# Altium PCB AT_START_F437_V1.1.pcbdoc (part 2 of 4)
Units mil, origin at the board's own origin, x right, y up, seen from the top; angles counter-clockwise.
Board outline 10746.75 x 3533.35 mil, 2 copper layers (Top Layer, Bottom Layer); 198 components, 235 nets, 885 pads, 1100 vias.
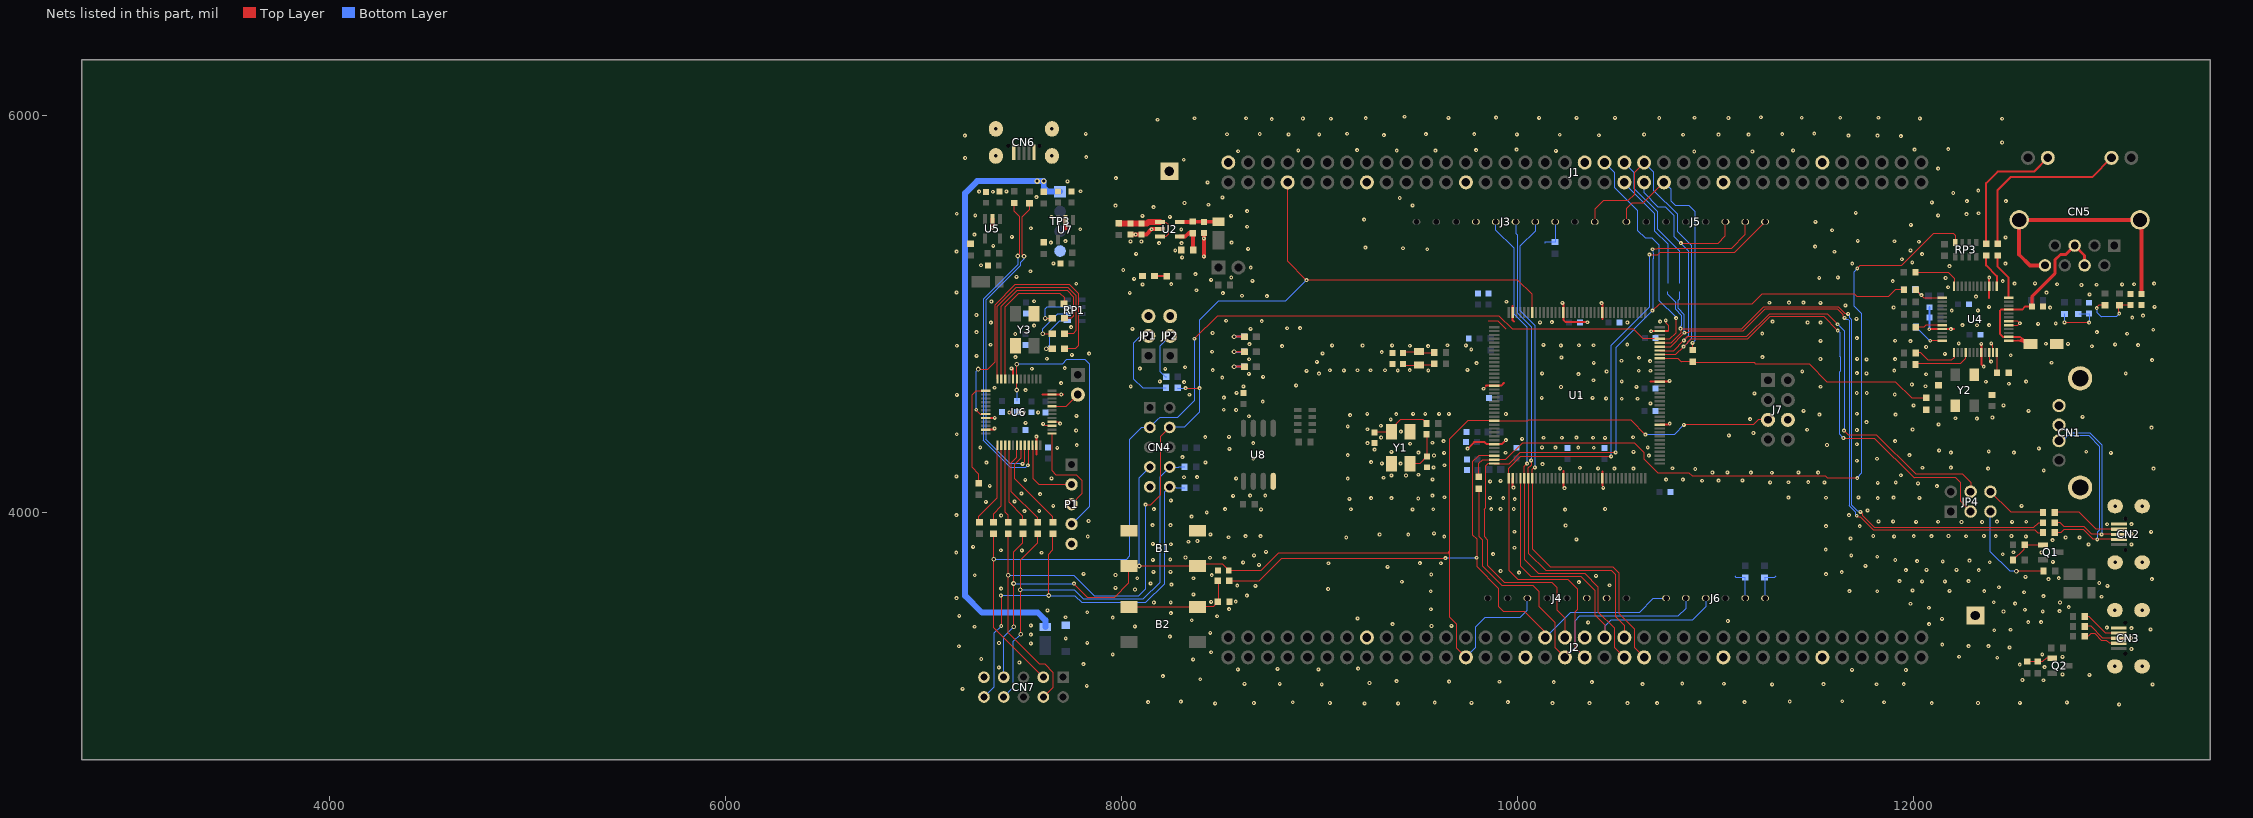
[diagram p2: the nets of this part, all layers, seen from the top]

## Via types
v1: diameter 19.69, hole 7.87, Top Layer to Bottom Layer, 1002 vias
v2: diameter 23.62, hole 11.81, Top Layer to Bottom Layer, 48 vias
v3: diameter 24, hole 12, Top Layer to Bottom Layer, 18 vias
v4: diameter 19.68, hole 7.87, Top Layer to Bottom Layer, 16 vias
v5: diameter 35.43, hole 19.69, Top Layer to Bottom Layer, 12 vias
v6: diameter 27.56, hole 15.75, Top Layer to Bottom Layer, 2 vias
v7: diameter 35.43, hole 19.68, Top Layer to Bottom Layer, 2 vias

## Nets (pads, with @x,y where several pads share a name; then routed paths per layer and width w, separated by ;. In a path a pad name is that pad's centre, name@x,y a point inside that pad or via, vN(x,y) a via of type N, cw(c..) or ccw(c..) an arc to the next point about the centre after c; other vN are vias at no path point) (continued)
$1N457: LD2.1 RP1.7 | length 200.3
  Top Layer w6: v2(7615.11,4977.88) 7649.1,4977.86 LD2.1@7649.5,4977.47
  Bottom Layer w6: v2(7615.11,4977.88) 7615.1,5027.16 7624.4,5036.47 RP1.7@7727.7,5036.47
$1N458: LD3.1 RP1.6 | length 229
  Top Layer w6: v2(7602.55,4901.02) LD3.1@7649.97,4901.01
  Bottom Layer w6: v2(7602.55,4901.02) 7602.6,4926.77 7676.8,5000.97 RP1.6@7727.7,5000.97
$1N459: LD4.1 RP1.5 | length 239.4
  Top Layer w6: v2(7619.44,4825.4) 7619.8,4825.06 LD4.1@7649.9,4825.06
  Bottom Layer w6: v2(7619.44,4825.4) 7636.6,4842.56 7636.6,4915.06 7687.1,4965.56 RP1.5@7727.7,4965.56
$1N484: J9.2 U6.44 | length 154.6
  Top Layer w6: U6.44@7648.8,4534.27 7720.2,4534.27 J9.2@7779,4593.06
$2N452: C1.2 R1.1 Y1.1 | length 309.1
  Top Layer w6: C1.2@9277.76,4402.85 9281,4406.06 Y1.1@9362.56,4406.07 9362.6,4420.4 9410.96,4468.86 9520.8,4468.86 R1.1@9542.2,4447.36
$2N453: C2.2 R3.1 Y1.3 | length 211.7
  Top Layer w6: Y1.3@9457.04,4244.65 9504.8,4244.66 C2.2@9541.38,4281.21 R3.1@9542.2,4393.36
$2N511: C3.2 R5.1 X1.2 | length 164.3
  Top Layer w6: C3.2@9421.9,4802.56 9429.9,4810.47 X1.2@9501.97,4810.51 9507.2,4805.27 R5.1@9580.8,4805.27
$2N512: C4.2 R6.1 X1.1 | length 163.6
  Top Layer w6: C4.2@9422.3,4746.97 9426.7,4742.56 X1.1@9501.97,4742.59 9575.7,4742.56 R6.1@9581.6,4748.56
$2N701: JP1.2 R13.1 | length 455.4
  Bottom Layer w6: JP1.2@8135.8,4889.36 8096.7,4889.36 8059.8,4852.36 8059.8,4674.36 8106.7,4627.36 R13.1@8226.3,4627.36
$2N702: JP2.2 R14.1 | length 244.9
  Bottom Layer w6: R14.1@8227.3,4683.36 8221.3,4683.36 8193.8,4710.86 8193.8,4837.36 JP2.2@8245.8,4889.36
$3N58: C5.1 C6.1 F1.2 U2.1 U2.3 | length 369.5
  Top Layer w6: U2.1@8180.7,5465.36 8224.1,5463.97 8235.8,5452.36 8235.8,5402.36 8223.7,5390.36 U2.3@8193.75,5390.35
  Top Layer w30: F1.2@7985.8,5458.66 7987.9,5456.47 C5.1@8045.75,5456.5 C6.1@8100.75,5456.5 8127.4,5456.47 8136.2,5465.36 8180.7,5465.36 U2.1@8193.75,5465.35
$3N81: R15.1 R16.1 U2.4 | length 160.8
  Top Layer w20: U2.4@8293.75,5390.35 8320.7,5390.36 8340.3,5409.86 8359.8,5409.86 8359.8,5323.86 R15.1@8359.2,5323.36
$3N82: C7.1 D1.2 R16.2 U2.5 | length 196.6
  Top Layer w20: U2.5@8293.75,5465.35 8324.3,5465.36 8324.7,5464.86 8359.7,5464.86 8361,5466.06 D1.2@8489.7,5466.06
$3N119: LED1.1 R10.2 | length 64.5
  Top Layer w10: LED1.1@8165.8,5192.16 R10.2@8230.3,5191.36
$3N184: B2.2 B2.4 R18.2 R19.1 | length 568
  Top Layer w6: B2.4@8037.5,3520.97 8384,3520.97 8461.8,3520.97 8488.2,3547.36 8487.2,3548.36 R19.1@8487.2,3653.36
$3N504: LED2.1 R26.2 | length 104.4
  Top Layer w10: v3(8568.19,4733.99) 8568.8,4734.56 LED2.1@8620.5,4734.56
  Bottom Layer w10: v3(8568.19,4733.99) 8568.6,4734.36 R26.2@8619.9,4734.36
$3N505: LED3.1 R27.2 | length 104.1
  Top Layer w10: v3(8568.19,4809.39) LED3.1@8620.56,4809.56
  Bottom Layer w10: v3(8568.19,4809.39) R27.2@8619.9,4809.36
$3N506: LED4.1 R28.2 | length 104.1
  Top Layer w10: v3(8568.19,4885.69) LED4.1@8620.56,4885.86
  Bottom Layer w10: v3(8568.19,4885.69) R28.2@8619.9,4885.66
$3N630: CN2.4 R29.2 | length 361.6
  Top Layer w6: R29.2@12710.1,3998.36 12836,3998.36 12921.1,3913.26 CN2.4@13036.5,3913.26
$3N657: Q1.1 R32.2 R33.1 | length 193.9
  Top Layer w6: R33.1@12503.1,3758.36 12558.1,3813.36 12558.1,3834.36 Q1.1@12653.23,3833.76
$3N714: Q2.1 R36.1 R37.2 | length 134.1
  Top Layer w6: R37.2@12572.7,3243.07 12650.3,3243.07 12668.2,3260.97 Q2.1@12699.4,3260.97
$3N779: CN3.4 R38.2 | length 208.5
  Top Layer w6: R38.2@12862,3472.36 12885.3,3472.36 12969.2,3388.47 CN3.4@13035.7,3388.47
$3N780: CN3.3 R39.2 | length 198.4
  Top Layer w6: R39.2@12862,3422.36 12895.58,3422.36 12954.98,3362.86 CN3.3@13035.7,3362.86
$3N781: CN3.2 R40.2 | length 198.7
  Top Layer w6: R40.2@12862,3372.36 12882.13,3372.36 12894.71,3384.94 12915.93,3384.94 12950,3350.86 12975.53,3350.86 12989.13,3337.26 CN3.2@13035.7,3337.26
$4N269: J6.5 R57.2 | length 163
  Bottom Layer w6: 11095.8,3678.07 11102,3671.86 11149.7,3671.86 J6.5@11149.36,3565.36
$4N270: J6.6 R59.2 | length 168.5
  Bottom Layer w6: J6.6@11249.36,3565.36 11249.35,3666.94 R59.2@11246.6,3669.69 11298.91,3669.69 11306.5,3677.28
$4N339: J3.3 R61.2 | length 161.8
  Bottom Layer w6: 10135.7,5356.66 10135.7,5361.86 10188.8,5361.86 J3.3@10189.36,5465.36
$5N126: R62.2 U4.24 | length 249.5
  Top Layer w6: R62.2@12007.3,5211.36 12173.8,5211.36 12203.5,5181.66 U4.24@12203.48,5140.68
$5N184: R69.2 U4.36 | length 162.1
  Top Layer w6: v4(12083.46,4865.2) 12083.59,4865.06 U4.36@12144.43,4865.09
  Bottom Layer w6: R69.2@12011.07,4934.54 12080.42,4865.2 v4(12083.46,4865.2)
$5N285: C46.1 R76.1 R77.1 | length 266.4
  Top Layer w6: v1(12761.53,4957.78) 12762.32,4956.99 v1(12886.04,4956.99)
  Bottom Layer w6: v1(12761.53,4957.78) 12761.5,5001.66 R76.1@12761.7,5001.86 ; R77.1@12833.6,5001.97 C46.1@12886.03,5002 v1(12886.04,4956.99)
$5N306: C47.1 R78.1 R79.1 | length 299
  Top Layer w6: v1(12924.26,5030.28) 12924.27,5033.44 12934.11,5043.28 R78.1@12964.32,5043.28 ; v1@13038.11,5001.95 13036.55,5003.52 13036.55,5042.56 13039.75,5045.77 C47.1@13094.09,5045.77
  Bottom Layer w6: v1(12924.26,5030.28) 12924.26,5008.22 12946.32,4986.15 13022.36,4986.15 v1(13038.12,5001.91)
$5N309: CN5.10 R80.1 | length 915.5
  Top Layer w10: R80.1@12423.8,5352.86 12423.8,5626.36 12488.8,5691.36 12901.1,5691.36 CN5.10@12998.63,5788.77
$5N310: CN5.11 R81.1 | length 672.4
  Top Layer w10: R81.1@12365.8,5352.86 12365.8,5661.36 12423.8,5719.36 12607.5,5719.36 CN5.11@12676.9,5788.77
$5N573: R74.2 U4.48 | length 103.7
  Top Layer w6: U4.48@12420,4806.06 12420,4705.56 R74.2@12422.3,4703.36
ATLINK_5V: CN6.1 D3.2 F2.1 TP3.1 | length 3070.1
  Bottom Layer w30: D3.2@7615.2,3419.26 7615.2,3454.57 7576.9,3492.86 7294.4,3492.86 7210.5,3576.76 7210.5,5610.56 7271,5670.97 v6(7607.18,5671.02) 7607.2,5637.36 7626.6,5618.06 TP3.1@7689.6,5618.06
  other v6: 7573.2,5671.56
ATLK_RX: CN4.10 CN7.10 R25.1 R48.1 | length 2306.3
  Top Layer w6: v1(7390.2,3578.57) 7392.2,3576.57 v1(7392.2,3424.57) ; v2@7634.7,3576.07 v2(7632.2,3578.57) 7632.2,3787.47 7653.2,3808.47 R48.1@7653.2,3892.07
  Bottom Layer w6: CN7.10@7305,3065.97 7355.5,3116.57 7355.5,3387.97 v1(7392.2,3424.57) ; v1(7390.2,3578.57) v2(7632.2,3578.57) 7763.47,3578.57 7797.92,3544.11 8122.97,3544.11 8217.14,3638.28 8217.14,4101.72 CN4.10@8242.77,4127.36 ; CN4.10@8270.7,4127.56 8275.7,4122.47 R25.1@8319.7,4122.47
ATLK_TX: CN4.8 CN7.8 R24.1 R47.1 | length 2336.5
  Top Layer w6: v2(7490.2,3383.57) 7490.2,3759.16 7577.2,3846.16 R47.1@7577.2,3892.07
  Bottom Layer w6: CN7.8@7405,3065.97 7453.54,3114.58 7453.54,3346.91 v2(7490.2,3383.57) ; v2(7488.97,3607.01) 7760.63,3607.01 7806.2,3561.45 8109.97,3561.45 8194.68,3646.16 8194.68,4179.26 CN4.8@8242.77,4227.36 8288.4,4227.36 8290.5,4229.36 R24.1@8320.3,4229.36
AVDD18: C45.1 C48.2 CN5.4 CN5.5 U4.1 U4.2 U4.9 | length 1164
  Top Layer w10: U4.1@12479.07,4865.09 12531.8,4865.06 ; 12527.8,4865.36 C45.1@12589.37,4849.35 12536.6,4884.77 U4.2@12479.07,4884.77 12450,4884.77 12434.9,4899.86 12434.9,5015.66 12441.8,5022.56 U4.9@12479.07,5022.56 12547,5022.56 12561.8,5037.36 C48.2@12598.2,5037.36
  Top Layer w15: 12542.1,4869.97 12570.1,4849.36 C45.1@12589.37,4849.35 ; C48.2@12598.2,5037.36 12598.2,5089.86 12712.3,5203.97 12712.3,5272.56 12740.7,5300.97 12767.8,5300.97 12812.8,5345.86 12862.8,5295.86 CN5.4@12862.8,5245.86
BOOT0: CN4.4 CN7.4 J1.66 R13.2 R45.1 U1.138 | length 5766.1
  Top Layer w6: R45.1@7428.2,3892.07 7428.2,3390.57 7587.8,3230.97 7613.5,3230.97 7655.6,3188.97 7655.6,3116.57 CN7.4@7605,3065.97 ; v1(8121.75,4037.36) 8147.35,4037.36 8197.04,4087.05 8197.04,4381.63 CN4.4@8242.77,4427.36 ; v1(8323.2,4625.98) v1(8394.07,4625.98) ; J1.66@8838.7,5664.56 8838.7,5266.36 v1(8933.8,5171.36) 10000.7,5171.36 10073.4,5098.66 U1.138@10073.36,5007.69
  Bottom Layer w6: v2(7427.75,3681.36) 7757.75,3681.36 7862.76,3576.35 8085.76,3576.35 8121.75,3612.35 v1(8121.75,4037.36) ; CN4.4@8242.77,4427.36 8315.3,4427.56 8392.8,4505.06 8392.8,4968.36 8489.4,5064.97 8827.4,5064.97 v1(8933.8,5171.36) ; R13.2@8281.3,4627.36 8282.6,4625.97 v1(8323.2,4625.98)
CRS_DV: R70.2 U4.37 | length 244.4
  Top Layer w6: R70.2@12007.9,4803.66 12035.8,4803.66 12074.04,4765.51 12190.63,4765.51 12203.5,4778.39 U4.37@12203.5,4806.06
EMAC_GND: C49.2 CN5.8 CN5.SH1 CN5.SH2 | length 1317
  Top Layer w20: CN5.8@12662.75,5245.9 12586.21,5245.9 12532.83,5299.27 12532.83,5475.82 CN5.SH1@13142.72,5475.79 ; CN5.SH1@13142.7,5475.86 13151.2,5467.36 C49.2@13151.2,5100.77
EMAC_NRST: R71.2 U4.40 | length 287.7
  Top Layer w6: R71.2@12014.45,4752.51 12238.7,4752.51 12262.5,4776.32 U4.40@12262.5,4806.06
GND: B1.2 B1.4 C1.1 C2.1 C3.1 C4.1 C5.2 C6.2 C7.2 C8.2 C9.2 C10.2 C11.2 C12.2 C13.2 C14.2 C15.2 C16.2 C17.2 C18.2 C19.2 C20.2 C21.1 C22.2 C23.2 C24.2 C25.2 C26.2 C27.2 C28.2 C29.2 C30.2 C31.2 C32.2 C33.2 C34.2 C35.2 C36.2 C37.2 C38.2 C39.2 C40.2 C41.2 C42.2 C43.2 C44.2 C45.2 C46.2 C47.2 C48.1 C49.1 C50.2 C51.2 CN1.4 CN1.SH1 CN1.SH2 CN2.5 CN2.6 CN2.7 CN2.8 CN2.9 CN3.5 CN3.6 CN3.7 CN3.8 CN3.9 CN4.9 CN6.5 CN6.6 CN6.7 CN6.8 CN6.9 CN7.9 D4.2 J1.11 J1.22 J1.35 J1.48 J1.58 J1.71 J2.16 J2.31 J2.38 J2.51 J2.61 J3.7 J4.6 J4.7 J7.6 JP1.3 JP2.3 LED1.2 P1.5 R15.2 R18.1 R49.2 R51.2 R74.1 R82.2 T1.1 T2.1 TP3.4 U1.16 U1.31 U1.38 U1.51 U1.61 U1.83 U1.94 U1.107 U1.120 U1.130 U1.143 U2.2 U4.5 U4.6 U4.15 U4.33 U4.44 U4.46 U4.47 U5.2 U6.8 U6.20 U6.23 U6.35 U6.39 U6.40 U6.47 U7.2 U8.4 Y1.2 Y1.4 Y2.2 Y2.4 Y3.2 Y3.4 | length 3006.6
  Top Layer w6: v1(7603.68,4445.59) 7613.47,4435.8 U6.39@7648.77,4435.8 ; U6.40@7648.77,4455.48 7680.87,4455.48 v1(7689.97,4446.38) ; v1(9827.81,4622.49) 9843.9,4638.56 U1.16@9881.43,4638.57 ; 9852.63,4966.85 9898.73,4966.85 9938.92,4926.66 ; U1.38@9975,4171.06 9975,4127.77 v1(9979.11,4123.69) ; U1.51@10230.9,4171.06 10230.9,4127.16 v1@10236.8,4121.36 ; U1.61@10427.69,4171.06 10427.7,4126.66 v1@10432.2,4122.16 ; v1(10747.8,4968.03) 10747.8,4956.6 10760.87,4943.54 10760.87,4916.23 10758.8,4914.16 ; U4.46@12380.65,4806.03 12380.65,4770.12 v1(12390.78,4759.99) ; v1(12391.57,4851.4) 12400.33,4842.65 U4.47@12400.33,4806.03 ; U4.5@12479.1,4943.86 12526.2,4943.86 v1(12535.75,4953.35) 12525.6,4963.47 U4.6@12479.07,4963.52
  Top Layer w10: U6.23@7314.12,4416.1 7358.6,4416.06 v1(7358.6,4422.77) ; U6.20@7314.12,4475.16 v1(7359.8,4475.16) v1@7359.8,4476.36 ; v1(7443.7,4725.36) 7451.9,4725.36 U6.8@7451.9,4672.06 ; v1@7567.4,4384.86 7567.4,4384.16 v1(7570.19,4381.36) 7570,4381.16 U6.35@7570.03,4337.36 7570,4289.97 ; 7601.3,4592.56 U6.47@7648.77,4593.27 v1@7703.4,4593.77 ; v1(9747.83,4320.69) 9780.7,4353.56 9832.6,4353.56 9842.9,4343.27 U1.31@9881.43,4343.31 9920.8,4343.27 v1(9940.92,4363.39) ; 9841,4638.56 U1.16@9881.43,4638.57 9917.7,4638.56 9931.1,4651.97 ; U1.38@9974.94,4171.06 9974.9,4123.66 v1(9979.11,4123.69) ; 9974.9,5040.16 U1.143@9974.94,5007.69 9974.9,4968.36 9982.3,4961.06 ; v1(10226.14,5056.28) 10230.9,5051.56 10230.9,5007.66 10230.9,4971.47 10243.8,4958.56 v1(10352.62,4958.57) ; v1@10230.8,4128.86 U1.51@10230.84,4171.06 10230.8,4206.47 ; v1(10424.33,5055.49) 10427.7,5052.16 U1.120@10427.69,5007.69 10427.7,4974.77 ; 10427.7,4133.47 U1.61@10427.69,4171.06 10427.7,4204.06 ; 10669.8,4658.27 10718,4658.27 10762.7,4658.27 v1(10767.11,4662.68) ; v1(10673.99,4912.98) 10675.2,4914.16 U1.107@10718,4914.16 ; U1.83@10718.05,4441.73 10763.2,4441.66 v1(10768.29,4446.77) ; U1.107@10718.05,4914.16 10758.8,4914.16 ; v1(12078.34,4923.11) 12079.39,4924.16 12144.4,4924.16 v1(12187.94,4924.16) ; v1(12187.94,4924.16) 12202.4,4924.16 ; v1@12341.3,4854.16 12341.3,4806.06 12341.3,4747.23 v1(12353.74,4734.78) ; 12380.7,5081.86 U4.15@12380.65,5140.68 v1@12380.7,5184.77
  Top Layer w20: v1(7347.97,5435.7) U5.2@7348.2,5480.57 ; 7717,5432.16 U7.2@7716.98,5474.91 ; C5.2@8045.7,5401.47 v1(8071.33,5401.47) 8100.7,5401.47 8124.9,5401.47 v1(8151.7,5428.36) U2.2@8193.75,5428.35 ; v1(8415.7,5381.98) C7.2@8415.7,5409.86 ; v1(8415.7,5381.98) 8415.7,5291.36 v1(8415.75,5291.35)
  Bottom Layer w10: v1(12078.34,4923.11) 12079.25,4924.03 C42.2@12079.25,4982.35 C41.2@12079.25,5034.35
  other v1: 13037.33,3029.16 8472.41,3034.26 9227.14,3034.26 9396.04,3033.86 10175.95,3035.03 10362.96,3035.03 10554.69,3035.03 10704.69,3035.03 12091.34,3035.07 8668.48,3035.82 9052.33,3035.82 12324.59,3035.86 9766.9,3036.61 12536.17,3036.64 9581.47,3037.8 10918.08,3037.8 12773.35,3038.61 8134.23,3040.16 8864.54,3039.76 11850.61,3039.8 9950.76,3040.55 11146.03,3040.55 8299.19,3042.51 11373.98,3043.3 11639.34,3044.49 7197.07,3106.77 7823.99,3122.45 9011,3129.93 11285.01,3129.93 11812.57,3130.32 13206.66,3129.53 10631.07,3131.11 11544.46,3131.49 11949.89,3131.59 8620.84,3132.68 8798.79,3132.68 11041.31,3133.07 10831.07,3133.86 9251.94,3137.01 10182.25,3141.34 10374.77,3140.95 9907.45,3143.3 9653.91,3144.09 9388.55,3146.45 12654.76,3150.91 12549.17,3152.09 8397.22,3155.91 8208.24,3171.26 12887.22,3178.09 12751.29,3180.45 11688.28,3203.3 11960.93,3202.51 8586.98,3205.91 8994.07,3205.91 8788.16,3207.88 9194.07,3209.84 7380.38,3215.97 12660.67,3217.49 12535.38,3230.09 7807.38,3232.46 7484.3,3240.34 8361.39,3255.91 7291.63,3258.07 12421.91,3264.38 12229.24,3269.49 12751.29,3269.11 7955.49,3281.49 12649.24,3280.93 8451.96,3292.34 13098.8,3308.51 12484.16,3316.78 7178.95,3322.69 12276.91,3323.47 12376.99,3323.47 12144.14,3330.95 7542.2,3336.57 7381.07,3338.84 7826.54,3339.01 7718.2,3362.57 13097.62,3364.05 8244.32,3370.76 7542.2,3381.57 8447.63,3390.05 12406.93,3403.45 12489.28,3405.82 13196.51,3407.78 13099.59,3414.09 12975.87,3416.45 7258.14,3420.79 8067.3,3422.43 9565.01,3424.74 9665.88,3425.12 7542.2,3427.57 9368.8,3433.8 12077.94,3434.18 10355.48,3443.3 12578.32,3444.04 12643.73,3444.04 11061.78,3449.99 8354.3,3453.93 12142.95,3460.2 9192.29,3463.34 7955.49,3467.32 7717.15,3468.86 8482.26,3474.01 7180.52,3475.95 8249.45,3489.34 7826.54,3494.01 12453.43,3498.02 12651.61,3498.8 12736.71,3499.59 7625.96,3503.55 12561.78,3506.68 9561.86,3509.05 8543.37,3510.22 12076.76,3516.93 12782.81,3520.07 11983.78,3537.03 12512.13,3537.42 8163.16,3543.32 12738.68,3543.32 8248.26,3544.11 12404.18,3544.51 8452.36,3546.88 8576.47,3547.66 7166.34,3565.78 12949.08,3572.49 12654.76,3575.64 8633.2,3577.99 8362.97,3584.64 12557.44,3594.94 9561.47,3600.07 11815.93,3600.07 12356.11,3600.46 11674.88,3600.84 12181.57,3602.43 11994.81,3604.4 8067.69,3609.05 9042.96,3611.49 7391.71,3613.86 7969.27,3616.93 12429.79,3620.55 8676.15,3627.24 12978.23,3626.86 8584.34,3628.82 10464.14,3630.7 8251.81,3633.55 8147.01,3639.86 12936.86,3641.82 10309.42,3646.45 9415.69,3648.12 12042.09,3649.71 12157.14,3649.71 12277.31,3651.28 11928.62,3651.68 12680.76,3661.14 13202.33,3661.41 8079.11,3665.74 8362.97,3665.74 12732.38,3666.64 12564.53,3672.55 10395.64,3677.95 7258.54,3680.83 7969.27,3682.28 8455.51,3682.01 9563.83,3684.78 11557.08,3686.34 7808.17,3687.53 10007.47,3693.84 11636.66,3696.59 8160.91,3698.24 8247.21,3698.24 9914.14,3702.36 11960.53,3707.23 12328.53,3706.84 12064.55,3708.02 12216.24,3708.02 9343.58,3723.39 11755.65,3728.11 8693.88,3733.62 9044.54,3741.51 9506.7,3742.3 9612.29,3741.51 8613.75,3745.66 12384.08,3746.62 12703.22,3748.2 12146.89,3750.96 12016.87,3752.14 12281.64,3754.91 11906.95,3758.05 8158.43,3758.84 8245.9,3761.2 8446.44,3769.49 8520.52,3769.49 8322.73,3770.66 11815.93,3774.2 8668.66,3781.3 11684.73,3780.91 12449.49,3786.82 9876.35,3787.8 7165.16,3795.49 7596.59,3794.7 12503.46,3797.07 12645.3,3796.66 8729.34,3799.03 7390.55,3807.01 7496.91,3806.52 11555.89,3810.45 9984.22,3819.68 7250.26,3824.25 12883.28,3836.47 13099.19,3836.86 8249.45,3837.64 8158.04,3839.61 8337.31,3850.26 8383.01,3853.8 12701.25,3858.53 10296.67,3862.07 11681.19,3866.8 9134.37,3871.53 12766.66,3871.53 12837.97,3871.93 8540.92,3872.84 9629.63,3875.86 7829.41,3876.72 11900.64,3877.05 12566.5,3877.05 8626.35,3878.34 12089.37,3878.22 12264.7,3877.84 8701.94,3878.74 11795.84,3879.01 12000.33,3878.61 12175.66,3879.01 12354.14,3879.01 12414.42,3878.61 12492.83,3879.01 9447.61,3885.82 8448.42,3887.28 9302.73,3886.61 13100.77,3890.05 9577.62,3892.41 9983.44,3900.39 13198.48,3899.89 11557.08,3929.05 11727.68,3928.66 10242.3,3932.2 8156.4,3934.47 8247.21,3934.47 12977.05,3938.51 13099.59,3938.91 12241.45,3949.93 12345.86,3949.93 12012.54,3950.72 12122.86,3951.11 12496.77,3950.72 12568.08,3951.11 12420.72,3951.51 11822.24,3952.7 11896.31,3952.7 7833.26,3955.01 8353.52,3977.16 7391.71,3982.64 11673.31,3984.22 7165.95,3984.61 8429.9,3998.01 7509.12,4005.09 7584.37,4006.28 11767.47,4008.24 10240.13,4012.2 8704.12,4013.36 9469.27,4013.36 9158.01,4014.16 9574.07,4014.16 8163.36,4014.57 8523.27,4014.55 9866.82,4014.55 9914.14,4015.36 9980.29,4015.36 10441.31,4015.36 7654.9,4031.49 12545.23,4031.09 7315.27,4051.59 7460.26,4053.55 8249.45,4058.68 9985.41,4065.76 9149.98,4066.93 9498.03,4068.53 9927.1,4070.5 11818.69,4070.49 9260.21,4070.86 9362.57,4070.86 9860.51,4071.29 11557.08,4072.47 12028.3,4071.68 11366.77,4072.86 11898.28,4072.86 11720.98,4074.43 9630.29,4074.8 8563.46,4081.53 8648.96,4082.72 8725.4,4083.49 9569.74,4082.72 7588.31,4090.99 7494.3,4094.01 10236.78,4121.32 10432.21,4122.11 12116.95,4131.18 7334.58,4132.36 12021.6,4144.97 11818.3,4147.32 11274.97,4150.09 11367.17,4150.48 11548.8,4149.69 11909.31,4149.69 11467.24,4151.66 9861.3,4155.21 9913.76,4157.48 10931.26,4157.97 11014.93,4159.15 11134.71,4159.94 7513.85,4162.3 10749.38,4163.88 10834.48,4163.88 9570.53,4165.45 9142.1,4169.3 7646.23,4170.18 8578.04,4170.18 9323.2,4173.23 8315.33,4175.59 8381.47,4176.38 7165.95,4180.03 9436.17,4184.76 9362.1,4185.55 11934.92,4185.94 9498.82,4188.31 11178.05,4198.94 11283.64,4198.55 11517.28,4199.34 10983.81,4199.73 11059.06,4200.12 11417.99,4200.12 12656.73,4210.37 10897.13,4217.46 10584.68,4219.04 12375.81,4219.04 10488.94,4219.82 13210.99,4219.69 10214.72,4221.01 10406.2,4220.61 10781.68,4221.01 10314.14,4223.61 12043.67,4223.76 9575.65,4225.34 12187.87,4224.55 9630.29,4236.23 10125.56,4242.52 9408.99,4244.26 9314.43,4245.44 7317.64,4249.77 8423.59,4250.56 9260.21,4251.97 11712.71,4259.22 11814.75,4269.07 8664.72,4270.65 8307.45,4277.56 10663.09,4284.83 9577.62,4285.62 9142.1,4287.4 11977.87,4287.2 9629.11,4299.2 9938.92,4299.41 12995.96,4299.02 12187.87,4300.2 12506.22,4300.2 9498.82,4300.6 9362.89,4303.74 10585.08,4304.14 12871.07,4304.53 12378.96,4306.5 12128.38,4311.63 9278.18,4315.56 8544.07,4318.9 12631.91,4321.48 7675.39,4323.84 10190.68,4325.42 10384.14,4325.02 7286.51,4326.2 10122.92,4326.2 10306.13,4325.81 10657.18,4326.99 7773.55,4338.02 11562.2,4338.81 11713.1,4342.36 9457.45,4344.73 8664.72,4348.27 9241.93,4348.27 9569.74,4349.85 9626.35,4358.27 11905.77,4358.12 10022.45,4369.15 10131.19,4375.45 10223.78,4375.45 10380.99,4375.45 10441.27,4374.67 10296.67,4376.24 9310.88,4376.64 8422.41,4378.22 10583.11,4377.82 8542.49,4379.52 11066.5,4387.01 7167.92,4393.18 11190.52,4399.2 9410.56,4406.57 7770.55,4412.02 11713.49,4414.46 11461.33,4415.64 11994.81,4416.82 9241.14,4418.01 13200.84,4426.27 9142.1,4433.07 9309.31,4435.73 12125.62,4442.43 7515.42,4450.31 11761.56,4454.25 9359.34,4467.65 11173.98,4469.69 12318.68,4471.59 12210.72,4473.95 12397.48,4477.5 12853.34,4480.26 8643.05,4483.81 7771.55,4486.02 9154.07,4489.31 11523.98,4492.47 11908.52,4492.47 9386.92,4494.44 9940.52,4495.27 9240.36,4496.02 9472.03,4495.62 9533.49,4496.02 9603.62,4496.02 9652.87,4495.62 11713.49,4496.41 7433.47,4502.72 7507.54,4504.3 7578.86,4503.51 11444.46,4511.02 12579.9,4510.99 8578.83,4515.32 8516.18,4516.51 11999.93,4538.96 12453.43,4538.57 10670.18,4548.81 8712.79,4557.88 10525.98,4572.45 10605.57,4572.45 10446.78,4573.64 10121.62,4576.38 10314.54,4575.59 10378.23,4576.39 8516.97,4577.57 7168.31,4591.37 8342.43,4592.55 7695.52,4593.69 11904.19,4593.73 11195.24,4599.6 11712.31,4601.22 11762.74,4601.22 8580.8,4601.6 7515.47,4616.02 7359.01,4627.61 10218.87,4631.49 10599.26,4631.94 11529.89,4632.74 8046.14,4634.31 8615.47,4634.7 12059.43,4635.1 8881.08,4639.76 11990.48,4644.16 12480.61,4647.71 7694.44,4651.02 8315.64,4656.38 12364.78,4657.95 12567.29,4659.14 8193.1,4659.93 10525.98,4660.32 10382.56,4665.83 8508.64,4679.12 8715.15,4682.38 10306.66,4696.45 12062.97,4695.78 8643.05,4697.35 8996.86,4698.93 10123.59,4700.39 11761.56,4700.5 13070.82,4700.51 11713.49,4701.69 10449.54,4709.96 11436.98,4710.23 8934.62,4712.6 10611.39,4713.39 10670.44,4713.39 11901.83,4713.9 9051.63,4716.27 9122.94,4715.86 9191.5,4716.27 9257.3,4716.27 9330.19,4716.27 9394.8,4715.86 9548.46,4715.86 8460.23,4717.06 9455.09,4716.65 9745.86,4717.84 8220.68,4723.35 7547.34,4723.74 8092.63,4724.53 7713.21,4727.3 8321.23,4731.49 9792.74,4752.11 10384.53,4753.69 12696.42,4753.94 8986.59,4758.27 10669,4762.36 10524.4,4763.94 13203.9,4767.31 8644.23,4771.43 11761.96,4770.64 11528.71,4772.99 11714.28,4773.39 11905.77,4772.61 7622.97,4774.02 10613.05,4779.3 10220.84,4781.1 7463.81,4782.06 11235.8,4782.27 7267.73,4789.02 12490.12,4791.73 7749.07,4793.89 12157.05,4798.43 7836.55,4800.02 9015.38,4800.98 9313.64,4807.67 8457.48,4809.65 9765.56,4821.06 12062.96,4833.47 12899.43,4837.23 8811,4838.19 9548.07,4838.01 7168.31,4839.59 9455.87,4839.59 9217.11,4841.16 9063.06,4841.56 9366.44,4841.56 9644.99,4842.35 9738.37,4841.56 10218.66,4841.56 10308.88,4842.34 10383.74,4842.34 13133.08,4842.73 10130.4,4843.92 7338.52,4844.71 10553.56,4845.89 13017.24,4846.68 8645.41,4847.85 12341.3,4849.03 12779.26,4849.05 12667.37,4849.82 12227.66,4851.4 11982.99,4863.23 11529.89,4864.41 11905.77,4865.2 11713.49,4878.2 7463.02,4899.07 13077.92,4900.27 11235.18,4901.05 8459.45,4904.2 7267.46,4909.02 12925.04,4908.93 13209.41,4920.86 8054.31,4925.19 8651.33,4924.69 8835.72,4928.23 8901.52,4928.62 7745.13,4933.76 7557.98,4941.64 12319.65,4943.31 12245.64,4944.1 12380.67,4944.1 12627.97,4950.3 12717.41,4953.06 7339.7,4956.6 10554.35,4957.39 11464.09,4957.39 11529.89,4956.6 10113.07,4958.18 10172.56,4958.97 11287.58,4961.33 10719.04,4961.73 8707.67,4964.09 8527.61,4966.06 11711.13,4975.91 13103.53,4981.82 13157.9,4992.06 7266.89,4995.02 12192.09,5017.31 12324.38,5018.1 11898.28,5033.04 12688.64,5032.65 12380.67,5036.22 13216.5,5035.82 11655.18,5043.28 11529.1,5056.29 11271.43,5057.07 11443.21,5057.47 11370.32,5057.86 9942.86,5061.81 7342.85,5063.38 7558.37,5064.56 12314.53,5088.19 8733.44,5090.15 8608.24,5092.52 12888.4,5098.84 8511.85,5105.53 8041.41,5106.72 12670.52,5107.9 7167.13,5109.48 8377.89,5120.11 12173.59,5135.03 12846.64,5146.52 12923.47,5147.69 8106.03,5149.66 12724.5,5150.45 13052.7,5150.06 13113.38,5150.45 8250.63,5150.85 7771.13,5152.81 12509.77,5153.2 13214.14,5153.53 12612.6,5155.18 11894.34,5165.82 8660.39,5167.4 12449.49,5166.6 8451.96,5172.12 8063.08,5177.24 12160.99,5181.89 11522.8,5182.76 8553.97,5184.35 12381.32,5183.94 11616.96,5184.73 7469.33,5187.49 8373.16,5201.27 7539.55,5216.02 8008.64,5222.44 8652.51,5234.38 12180.68,5241.73 7290.06,5246.59 11689.85,5254.47 12462.56,5254.32 7656.08,5255.65 11992.84,5260.38 11940.04,5276.53 8305.79,5286.39 12042.48,5302.54 8073.6,5303.94 11599.23,5314.36 7166.73,5315.14 8271.12,5321.44 11983.78,5321.05 9543.74,5326.97 8638.95,5328.73 9421.23,5332.27 9231.47,5335.03 11502.31,5340.36 7351.91,5344.3 8189.95,5357.69 8303.42,5357.69 7643.08,5360.85 8555.88,5360.62 12026.33,5365.18 8100.12,5366.36 8044.96,5367.15 7715.97,5368.34 11902.61,5367.55 11717.43,5369.52 12463.75,5387.4 7446.2,5389.56 7256.57,5401.43 11588.2,5423.1 7791.22,5428.23 8301.55,5427.56 7541.82,5432.94 8633.6,5440.82 11986.14,5450.29 11503.49,5465.26 9224.78,5476.38 7647.02,5490.48 8243.92,5490.35 8105.24,5495.2 8553.12,5495.66 7260.9,5498.35 12123.65,5498.35 12266.5,5504.72 7167.52,5506.23 12327.92,5509.05 11707.58,5510.57 8633.99,5519.62 8162.18,5540.15 7969.27,5547.64 9469.27,5548.78 8438.16,5551.97 8317.69,5560.62 12092.13,5564.15 12268.86,5570.47 12465.71,5570.07 9404.75,5586.02 8508.7,5589.36 7570.19,5590.55 12199.69,5611.03 7280.6,5618.12 7349.94,5617.73 7418.11,5618.91 7792.8,5620.1 12325.95,5622.82 8434.23,5664.95 7727,5669.74 7971.23,5686.6 12123.65,5733.97 8313.75,5779.12 7209.55,5788.02 7821.55,5792.02 10891.7,5820.85 11185.8,5820.85 8588.16,5822.05 10192.88,5824.01 8892.1,5825.98 9389.34,5825.59 9585.01,5825.59 11390.91,5826.38 9189.34,5827.94 9790.13,5827.94 9995.25,5829.91 12004.3,5829.91 12174.38,5833.06 12446.42,5866.14 11935.4,5898.81 7208.55,5901.02 11670.44,5901.18 11817.29,5901.18 10410.14,5902.99 9324.38,5903.53 10212.57,5905.11 10835.8,5905.51 11014.14,5905.9 11166.11,5906.3 8843.28,5907.48 8998,5907.48 9996.43,5907.48 10638.55,5906.69 8532.26,5907.86 11336.19,5908.27 8698,5909.05 9536.59,5908.65 9780.68,5908.65 7819.28,5910.02 9139.34,5910.23 11497.61,5911.02 8182.26,5981.1 8758.24,5984.64 9057.06,5986.22 12446.42,5986.22 8915.72,5987.4 12031.46,5987.78 8369.27,5988.57 8628.71,5988.57 9233.04,5988.97 10714.93,5989.76 11064.14,5989.76 9649.97,5990.55 10108.63,5990.55 10297.61,5990.55 10491.7,5990.55 10893.28,5990.94 11434.61,5990.94 11629.1,5990.94 11821.23,5990.94 9891.7,5992.11 11227.92,5993.69 9429.5,5996.06
LD1: LD1.2 U6.10 | length 732.6
  Top Layer w6: U6.10@7412.5,4672.06 7412.5,5036.86 7481.6,5105.97 7689,5105.97 7710,5085.06 LD1.2@7710,5052.06
LD2: LD2.2 U6.11 | length 927.9
  Top Layer w6: U6.11@7392.9,4672.06 7392.9,5038.56 7474.4,5120.06 7725,5120.06 7757,5088.06 7757,4988.06 7746.9,4977.97 LD2.2@7710.9,4977.97
LD3: LD3.2 U6.12 | length 1064.4
  Top Layer w6: U6.12@7373.2,4672.06 7373.2,5039.77 7469.4,5135.97 7728.5,5135.97 7769,5095.47 7769,4915.06 7755,4900.97 LD3.2@7710.97,4901.01
LD4: LD4.2 U6.19 | length 1479.6
  Top Layer w6: v4(7266.42,4516.9) 7266.42,4514.21 7285.76,4494.86 U6.19@7314.1,4494.86 ; v2@7276,4722.06 7323.04,4722.06 7361.2,4760.22 7361.2,5047.86 7464.3,5150.97 7735.9,5150.97 7781,5105.97 7781,4840.97 7765,4825.06 LD4.2@7710.9,4825.06
  Bottom Layer w6: v4(7266.42,4516.9) 7265.55,4517.77 7265.55,4711.59 v2(7275.97,4722.02)
LED_G: R80.2 U4.12 | length 239.1
  Top Layer w10: R80.2@12423.8,5297.86 12423.8,5239.36 12479.1,5184.06 U4.12@12479.1,5081.66
LED_Y: R81.2 U4.13 | length 179.6
  Top Layer w10: R81.2@12365.8,5297.86 12365.8,5245.36 12420,5191.06 U4.13@12420.02,5140.68
M-ATLK_RX: R48.2 U6.31 | length 483.9
  Top Layer w6: U6.31@7491.29,4337.36 7491.3,4271.36 7459,4238.97 7459,4169.66 7650,3978.66 R48.2@7650,3945.97
M-ATLK_TX: R47.2 U6.30 | length 457.3
  Top Layer w6: U6.30@7471.6,4337.36 7471.6,4275.66 7444.2,4248.27 7444.2,4102.27 7576,3970.47 R47.2@7576,3945.97
M-NRST: C22.1 P1.4 U6.7 | length 1418.3
  Top Layer w6: v2(7470.48,4616.02) 7471.6,4617.16 7471.6,4672.06 7470.5,4673.16 v2@7470.5,4747.06
  Bottom Layer w6: v2(7470.48,4616.02) 7470.5,4560.36 C22.1@7470.8,4560.06 ; v2(7470.77,4747.02) 7699.55,4747.02 7720.56,4768.02 7817.55,4768.02 7838.55,4747.02 7838.55,4030.42 P1.4@7747.7,3939.57
M-SWCLK: P1.3 U6.37 | length 503.4
  Top Layer w6: U6.37@7648.8,4396.47 7648.8,4207.47 7669.7,4186.56 7773,4186.56 7802,4157.56 7802,4093.86 P1.3@7747.7,4039.57
M-SWDIO: P1.2 U6.34 | length 376.2
  Top Layer w6: U6.34@7550.34,4337.36 7550.3,4171.94 7582.68,4139.56 P1.2@7747.7,4139.56
M-USB_D+: R11.2 U6.33 | length 1679.1
  Top Layer w6: R11.2@7458.2,5563.06 7458.2,5518.77 7486.09,5491.03 7486.09,5303.54 v2@7475.68,5293.13 ; v4@7526.88,4236.42 7530.7,4240.24 U6.33@7530.66,4337.36
  Bottom Layer w6: v2(7475.63,5293.08) 7475.63,5248.17 7301.88,5074.41 7301.88,4362.11 7440.62,4223.37 7513.85,4223.37 v4@7526.85,4236.37
  other v4: 7526.85,4236.37
M-USB_D-: R12.2 U6.32 | length 1629.9
  Top Layer w6: v4(7500.06,4243.46) 7511,4254.43 U6.32@7510.97,4337.36 ; v2(7507.15,5292.29) 7498.09,5301.45 7498.09,5492.36 7535.2,5529.62 R12.2@7535.2,5562.06
  Bottom Layer w6: v4(7500.06,4243.46) 7437.5,4243.46 7313.88,4367.09 7313.88,5069.44 7488.92,5244.49 7488.92,5258.64 7507.15,5276.87 v2(7507.15,5292.29)
M_ATLK_BOOT0: R45.2 U6.27 | length 395.7
  Top Layer w6: U6.27@7412.5,4337.36 7412.5,3998.16 7428,3982.76 R45.2@7428,3948.07
M_ATLK_NRST: R46.2 U6.28 | length 419.2
  Top Layer w6: U6.28@7432.23,4337.36 7432.2,4048.86 7502,3979.16 R46.2@7502,3947.07
M_ATLK_SWCLK: R41.2 U6.25 | length 427
  Top Layer w6: R41.2@7280,3948.97 7280,3978.47 7373.2,4071.66 U6.25@7373.18,4337.36
M_ATLK_SWDIO: R44.2 U6.26 | length 404.5
  Top Layer w6: R44.2@7354,3948.97 7354,3992.47 7392.9,4031.36 U6.26@7392.86,4337.36
M_ATLK_SWO: R52.2 U6.13 | length 542.1
  Top Layer w6: R52.2@7279.8,4141.97 7279.8,4191.77 7244.75,4226.82 7244.75,4591.21 7266.5,4612.97 U6.13@7314.12,4612.97
MDINTR: R83.2 U4.32 | length 138.6
  Top Layer w6: R83.2@12010.29,4932.96 12050.36,4932.96 12061.23,4943.82 U4.32@12144.43,4943.82
MDIO: R63.2 R72.1 U4.25 | length 193.3
  Top Layer w6: R63.2@12010.29,5123.27 v4(12038.43,5095.12) 12051.93,5081.62 U4.25@12144.43,5081.62
  Bottom Layer w6: R72.1@12008.32,5123.66 12009.89,5123.66 v4(12038.43,5095.12)
NRST: B1.1 B1.3 C40.1 CN4.7 CN7.7 J2.25 J4.3 J7.5 R46.1 U1.25 | length 7077.9
  Top Layer w6: v2(7456.2,3420.57) 7456.2,3799.76 7502.2,3845.76 R46.1@7502.2,3892.07 ; v1@7759.7,3638.36 7827.8,3570.36 7964.4,3570.36 8037.5,3643.47 8037.5,3727.76 B1.1@8384.03,3727.78 8394.6,3738.36 8507.8,3738.36 C40.1@8541.25,3705.36 8704.8,3705.36 8793.8,3794.36 9649.2,3794.36 9649.2,3795.47 9655.8,3801.97 ; 9649.23,3794.36 9655.8,3787.8 ; J2.25@9738.72,3266.46 9689.8,3315.47 9689.8,3436.66 9655.8,3470.66 9655.8,3787.8 ; v1@10644.7,4391.36 10570.8,4465.36 10056.2,4465.36 10052.3,4461.36 U1.25@9881.43,4461.41 9749.2,4461.36 9655.8,4367.97 9655.8,3801.97 ; v1@10839.7,4440.36 11188.6,4440.36 11214.2,4465.97 J7.5@11264.4,4465.97 ; 9655.8,3787.8 9655.8,3801.97
  Bottom Layer w6: CN7.7@7405,3165.97 7404.98,3369.34 v2(7456.2,3420.57) ; v2(7454.75,3639.36) 7455.75,3638.36 v1@7759.75,3638.36 ; v3(8088.75,3727.36) 8088.75,4173.33 CN4.7@8142.77,4227.36 ; J2.25@9738.72,3266.46 9788.8,3316.47 9788.8,3420.36 9836.8,3468.36 10012.9,3468.36 10049.4,3504.86 J4.3@10049.36,3565.36 ; v1(10644.75,4391.35) 10790.75,4391.35 v1@10839.75,4440.35
  other v1: 7759.75,3638.36 10839.75,4440.35
OTG1_D+: CN1.3 CN2.3 R30.2 | length 1059.7
  Top Layer w6: R30.2@12710.1,3946.36 12740.72,3946.36 12761.33,3925.75 12862.15,3925.75 12900.24,3887.66 v1(12949.08,3887.68) CN2.3@13036.5,3887.66
  Bottom Layer w6: CN1.3@12733.78,4439.26 12742.29,4439.27 12780.88,4400.67 12888.8,4400.67 12949.1,4340.37 v1(12949.08,3887.68)
OTG1_D-: CN1.2 CN2.2 R31.2 | length 1065.8
  Top Layer w6: R31.2@12710.1,3896.36 12743.09,3896.36 12758.05,3911.32 12858.14,3911.32 12907.3,3862.07 v1(12926.62,3862.07) CN2.2@13036.5,3862.07
  Bottom Layer w6: CN1.2@12733.78,4360.52 12752.9,4360.52 12780.05,4387.67 12882.86,4387.67 12937.1,4333.47 12937.1,3908.41 12926.6,3897.91 v1(12926.62,3862.07)
OTG1_ID: JP4.6 R29.1 | length 310.8
  Top Layer w6: JP4.6@12387.5,4102.77 12491.9,3998.36 R29.1@12655.1,3998.36
OTG1_VBUS: JP4.5 R34.1 | length 513.3
  Top Layer w5.98: v3(12518.44,3701.32) 12656.1,3701.26 R34.1@12657.1,3702.36
  Bottom Layer w5.98: JP4.5@12387.47,4002.74 12387.47,3800.77 12486.92,3701.32 v3(12518.44,3701.32)
PA0: J2.34 J6.1 R19.2 U1.34 | length 3215.1
  Top Layer w6: R19.2@8542.2,3653.36 8694.8,3653.36 8808.8,3767.36 v1@9634.7,3767.36 ; U1.34@9881.4,4284.27 9802.38,4284.27 9771.8,4253.62 9771.8,3885.76 9792.8,3864.76 v1(9792.75,3769.36) 9792.8,3725.36 9901.8,3616.36 9901.8,3523.36 9926.8,3498.36 10032.8,3498.36 10138.7,3392.36 J2.34@10138.72,3366.46
  Bottom Layer w6: v1(9634.75,3767.36) 9636.76,3769.36 v1(9792.75,3769.36) ; J2.34@10138.72,3366.46 10267.7,3495.36 10615.8,3495.36 10685.8,3565.36 J6.1@10749.36,3565.36
PA1: R84.2 RP3.4 U1.35 | length 3812.2
  Top Layer w6: R84.2@9804.17,4177.78 9804.17,4245.43 9823.3,4264.56 U1.35@9881.43,4264.56 9938.3,4264.56 10022.4,4348.66 10590.59,4348.66 10640.24,4299.02 10640.24,4266.87 10710.17,4196.97 10867.58,4196.97 10884.84,4179.7 11557.01,4179.7 11564.96,4171.76 v1(11714.68,4171.76) ; v1@11715.04,5230.42 11730.02,5245.41 11938.86,5245.41 12100.82,5407.36 12199.8,5407.36 12209.5,5397.66 RP3.4@12209.45,5361.35
  Bottom Layer w6: v1(11714.68,4171.76) 11714.68,4174.52 11735.16,4195 11735.16,5002.7 11696.16,5041.71 11696.16,5211.52 v1(11715.07,5230.43)
PA1_E: J2.35 J6.2 R84.1 | length 1968.1
  Top Layer w6: R84.1@9804.17,4118.46 9804.17,3877.8 9821.1,3860.86 9821.1,3728.07 9919.2,3629.97 10077.2,3629.97 10105.8,3601.36 10105.8,3525.36 10187.8,3443.36 10187.8,3317.47 J2.35@10238.72,3266.46
  Bottom Layer w6: J2.35@10238.72,3266.46 10287.8,3315.36 10287.8,3449.36 10311.8,3473.36 10809.7,3473.36 10849.4,3512.97 J6.2@10849.36,3565.36
PA2: J2.36 J5.2 R63.1 U1.36 | length 4858.7
  Top Layer w6: J2.36@10238.72,3366.46 10238.7,3466.36 10197.8,3507.36 10197.8,3619.36 10171.8,3645.36 9932.7,3645.36 9846.9,3731.16 9846.9,3861.47 9830.96,3877.4 9830.96,4015.34 9838.05,4022.43 9838.05,4233.22 9849.7,4244.86 U1.36@9881.43,4244.88 9957.66,4244.86 10014.16,4301.36 v1@10494.7,4301.36 ; v1(10680.82,5016.89) 10716.67,5052.74 11185.53,5052.74 11233.21,5100.41 11701.87,5100.41 11716.05,5086.23 11870.7,5086.23 11907.74,5123.27 R63.1@11950.97,5123.27 ; v1(10682,5327.36) 10703,5327.36 10708.91,5333.27 11080.3,5333.27 11149.3,5402.27 J5.2@11149.35,5465.35
  Bottom Layer w6: v1(10494.75,4301.35) 10494.75,4830.03 10680.82,5016.1 v1(10680.82,5016.89) 10683.58,5019.64 10683.58,5279.24 10687.12,5282.79 10687.12,5307.82 10683.58,5311.37 10683.58,5325.78 v1(10682,5327.36)
PA3: J2.37 J5.1 U1.37 | length 3567.5
  Top Layer w6: J2.37@10338.72,3266.46 10287.8,3317.47 10287.8,3493.36 10301.8,3507.36 10301.8,3613.26 10253.5,3661.57 9999.5,3661.57 9955.3,3705.76 U1.37@9955.25,4171.06 9955.3,4222.02 10014.64,4281.36 v1@10471.7,4281.36 ; v1@10665.49,5299.74 10707.17,5299.74 10719.8,5312.36 11096.4,5312.36 J5.1@11249.35,5465.35
  Bottom Layer w6: v1(10471.75,4281.35) 10471.75,4842.49 10666.24,5036.98 10666.24,5298.99 v1(10665.45,5299.78)
PA4: J2.40 J6.3 U1.40 | length 1779.9
  Top Layer w6: U1.40@10014.31,4171.06 10014.3,3727.76 10066,3676.07 10318.1,3676.07 10389.8,3604.36 10389.8,3480.57 10438.7,3431.66 J2.40@10438.72,3366.46
  Bottom Layer w6: J2.40@10438.72,3366.46 10438.7,3422.36 10469.8,3453.36 10881.8,3453.36 10949.4,3520.97 J6.3@10949.36,3565.36
PA5: J2.41 J3.6 U1.41 | length 2616.3
  Top Layer w6: v1(10047.75,4244.35) 10046.8,4244.36 10034,4231.56 U1.41@10033.99,4171.06 10034,3761.07 10104.8,3690.36 10337.7,3690.36 10405.8,3622.36 10405.8,3497.36 10487.8,3415.36 10487.8,3317.47 J2.41@10538.72,3266.46
  Bottom Layer w6: J3.6@9889.36,5465.36 9889.4,5423.77 9981.8,5331.36 9981.8,4998.06 10047.8,4932.06 v1(10047.75,4244.35)
PA6: J2.42 J3.5 U1.42 | length 2532
  Top Layer w6: v1(10067.75,4261.35) 10067.8,4237.36 10053.7,4223.27 U1.42@10053.68,4171.06 10053.7,3792.36 10140.8,3705.36 10471.8,3705.36 10491.8,3685.36 10491.8,3474.26 10538.7,3427.36 J2.42@10538.72,3366.46
  Bottom Layer w6: J3.5@9989.36,5465.36 9989.4,5408.77 9996.8,5401.36 9996.8,5007.06 10067.8,4936.06 v1(10067.75,4261.35)
PA7: J2.43 J3.4 U1.43 | length 2688.8
  Top Layer w6: v1@10086.7,4225.36 10083.8,4225.36 10073.4,4214.97 U1.43@10073.36,4171.06 10073.4,3814.26 10164.3,3723.36 10480.8,3723.36 10509.8,3694.36 10509.8,3489.36 10587.8,3411.36 10587.8,3317.47 J2.43@10638.72,3266.46
  Bottom Layer w6: v1@10086.7,4225.36 10086.7,4943.16 10011.8,5018.16 10011.8,5341.16 10089.4,5418.77 J3.4@10089.36,5465.36
  other v1: 10086.75,4225.35
PA8: R73.1 R85.2 U1.100 | length 1428.3
  Top Layer w6: U1.100@10718.05,4776.38 10808.26,4776.36 10825.92,4758.71 R85.2@10884.91,4758.71 10888.35,4755.27 11193.9,4755.27 11199.9,4749.27 11471.27,4749.27 11561.41,4659.13 11907.34,4659.13 11988.9,4577.58 R73.1@12064.04,4577.58
PA8_E: J1.28 J5.8 R85.1 | length 1268.5
  Top Layer w6: J5.8@10549.35,5465.35 10549.3,5532.77 10575.2,5558.66 10632.3,5558.66 J1.28@10738.7,5665.06 ; v4(10883.34,4854.16) 10883.34,4819.6 R85.1@10884.91,4818.03
  Bottom Layer w6: J1.28@10738.7,5665.06 10772.23,5631.54 10772.23,5572.4 10795.3,5549.36 10863.8,5549.36 10894.4,5518.77 10894.4,4865.23 v4(10883.34,4854.16)
PA9: J1.29 J3.1 JP4.3 U1.101 | length 3939.3
  Top Layer w6: J3.1@10389.36,5465.36 10389.4,5528.97 10431.8,5571.36 10555.8,5571.36 10587.8,5603.36 10587.8,5714.06 J1.29@10638.7,5765.06 ; U1.101@10718.05,4796.06 10798.5,4796.06 v1(10837.75,4835.35) 10877.3,4874.87 11162.11,4874.87 11272.93,4985.69 11547.32,4985.69 v1@11616.55,4916.46 ; v1(11645.33,4373.88) 11800.34,4373.88 12002.07,4172.15 12213.26,4172.15 12236.73,4148.68 12236.73,4053.48 JP4.3@12287.47,4002.74
  Bottom Layer w6: J1.29@10638.7,5765.06 10687.8,5715.97 10687.8,5623.77 10807.8,5503.77 10807.8,5416.27 10879.8,5344.27 10879.8,4877.36 v1(10837.75,4835.35) ; v1@11616.55,4916.46 11625.6,4907.4 11625.6,4786.66 11631.6,4780.66 11631.6,4713.56 11625.6,4707.56 11625.6,4393.64 v1@11645.36,4373.88
  other v1: 11616.57,4916.42
PA10: J1.30 J5.3 JP4.4 U1.102 | length 3575.9
  Top Layer w6: U1.102@10718.1,4815.77 10788.1,4815.77 v1@10839.7,4867.36 ; v1(10824.24,5358.09) 11013.4,5358.06 11049.3,5394.06 J5.3@11049.35,5465.35 ; v1(10839.75,4867.35) 10859.3,4886.87 11157.13,4886.87 11269.91,4999.73 11564.74,4999.73 v1(11616.18,4948.33) ; v1(11648.09,4410.91) 11668.58,4390.43 11811.21,4390.43 12009.39,4192.24 12246.18,4192.24 12287.47,4150.95 JP4.4@12287.47,4102.74
  Bottom Layer w6: J1.30@10638.7,5665.06 10638.7,5612.16 10710.8,5540.16 10747.4,5540.16 10791.1,5496.36 10791.1,5391.16 v1(10824.24,5358.09) ; v1(10824.24,5358.09) 10864.82,5317.51 10864.82,5146.12 10864.82,4892.42 v1@10839.75,4867.35 ; v1(11616.18,4948.33) 11648.09,4916.42 v1(11648.09,4410.91)
PA11/OTG1_D-: R31.1 U1.103 | length 3276.8
  Top Layer w6: U1.103@10718.05,4835.43 10773.13,4835.36 10842.31,4904.55 v1@10842.31,4905.39 ; v1(10842.36,4905.38) 10861.97,4905.38 10869.46,4912.87 11135.56,4912.87 11247.36,5024.77 11615.63,5024.77 11643.36,4997.03 11643.36,4988.55 v1@11651.28,4980.63 ; v1@11712.26,3981.4 11717.73,3975.94 11730.2,3975.94 11795.78,3910.35 12611.77,3910.35 12625.53,3896.36 R31.1@12655.1,3896.36
  Bottom Layer w6: 10818.94,5113.65 10818.94,5077.39 10810.45,5068.89 10810.45,5028.31 10842.41,4996.35 v1(10842.36,4905.38) ; v1@10841.8,4913.36 10842.31,4912.86 v1@10842.31,4905.39 ; v1(11651.24,4980.64) 11657.15,4974.73 11666.83,4974.73 11673.77,4967.79 11673.77,4031.17 11706.4,3998.54 11706.4,3987.36 v1(11712.31,3981.45)
PA11_E: J1.31 | length 726
  Bottom Layer w6: J1.31@10538.7,5765.06 10589.8,5713.97 10589.8,5633.36 10707.2,5515.97 10707.2,5428.66 10817.8,5318.06 10817.8,5154.66
PA12/OTG1_D+: R30.1 U1.104 | length 3277.6
  Top Layer w6: U1.104@10718.05,4855.11 10775.86,4855.06 10822.91,4902.11 v1@10822.91,4925.58 ; v1@10822.22,4926.28 v1@10822.91,4925.58 ; v1(11668.58,5000.34) 11664.19,5004.67 11652.69,5004.67 11619.92,5037.44 11243.07,5037.44 11130.5,4924.87 10823.62,4924.87 v1@10822.91,4925.58 ; v1(11730.83,4000.76) 11739.89,3991.7 11739.89,3983.21 11800.75,3922.35 12606.3,3922.35 12630.31,3946.36 R30.1@12652.89,3946.36
  Bottom Layer w6: 10758.58,5098.76 10758.58,5099.88 ; 10758.58,5112.86 10758.58,5099.88 ; v1@10822.22,4926.28 10822.22,4936.85 10829.8,4944.44 10829.8,4991.99 10798.45,5023.34 10798.45,5060.01 10758.58,5099.88 ; v1(11668.58,5000.34) 11674.58,4994.34 11674.58,4983.95 11685.77,4972.76 11685.77,4036.14 11716.03,4005.88 11725.71,4005.88 v1(11730.83,4000.76)
  other v1: 10822.27,4926.27
PA12_E: J1.32 | length 601.9
  Bottom Layer w6: J1.32@10538.7,5665.06 10538.7,5660.36 10692.6,5506.47 10692.6,5418.36 10759.7,5351.27 10759.7,5154.66
PA13/SWDIO: CN4.3 CN7.3 J1.33 R44.1 U1.105 | length 6398.5
  Top Layer w6: R44.1@7354,3888.07 7354,3763.16 v2(7354.75,3762.36) 7354.8,3416.26 CN7.3@7605,3165.97 ; v1(8367.75,4875.35) 8482.5,4990.06 9906.6,4990.06 9974.3,4922.36 10586.8,4922.36 10634.3,4874.77 U1.105@10718.05,4874.8 10769.2,4874.77 10800.4,4905.97 v1@10800.4,4979.56
  Bottom Layer w6: v2(7354.75,3762.36) 8025.8,3762.36 8041.8,3778.36 8041.8,4368.27 8101.07,4427.53 CN4.3@8142.77,4427.36 8180.5,4465.66 8192.7,4477.06 8281.7,4477.06 8367.8,4563.16 v1(8367.75,4875.35) ; J1.33@10438.7,5765.06 10489.8,5713.97 10489.8,5638.56 10607.1,5521.27 10607.1,5421.56 10645.8,5382.86 10680.4,5382.86 10716.3,5347.06 10716.3,5066.86 10800.4,4982.77 v1@10800.4,4979.56
  other v1: 10800.36,4979.52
